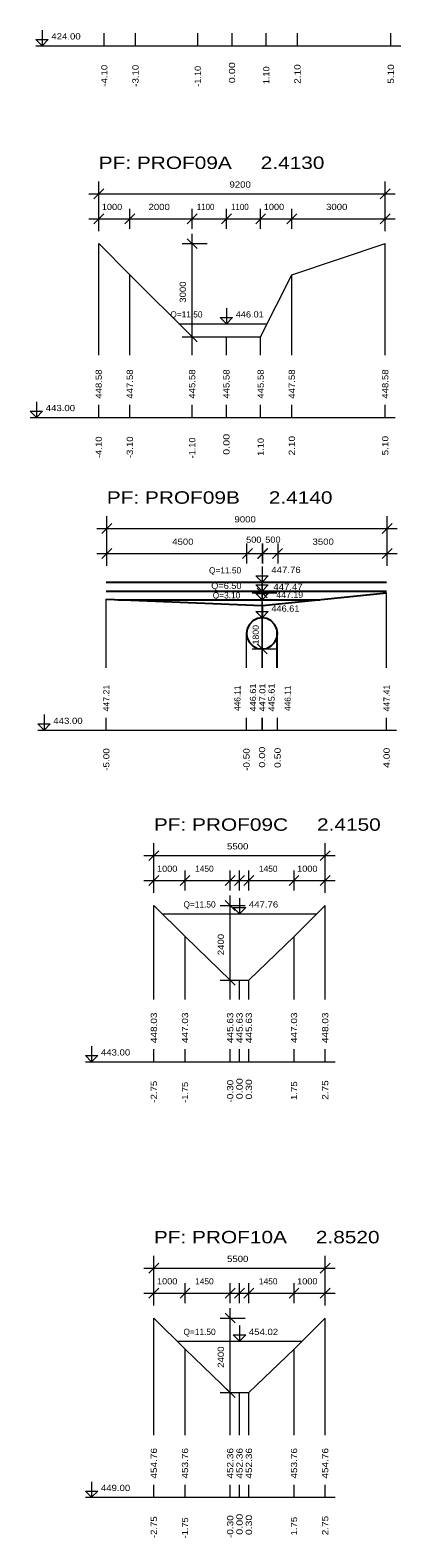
# Model space of a CAD drawing. Extents: x 7 to 442, y -393 to 441.
# Drawn here: x 175.32 to 187.22, y 47.32 to 95.79 of the extents above; entities that cross this region are included whole.
import ezdxf

# ---------------------------------------------------------------- set-up
doc = ezdxf.new("R2010")
doc.units = 0
doc.header["$LTSCALE"] = 0.08
doc.layers.add('7', color=7, linetype='Continuous', lineweight=13)

msp = doc.modelspace()

# ---------------------------------------------------------------- linework, layer by layer
at = {"layer": '7'}
for p, q in [((177.701, 95.289), (177.701, 95.689)), ((178.701, 95.289), (178.701, 95.689)), ((180.701, 95.289), (180.701, 95.689)), ((181.801, 95.289), (181.801, 95.689)), ((182.901, 95.289), (182.901, 95.689)), ((183.901, 95.289), (183.901, 95.689)), ((186.901, 95.289), (186.901, 95.689)), ((175.501, 95.289), (187.221, 95.289)), ((177.361, 90.366), (177.681, 90.686)), ((177.521, 89.326), (177.521, 90.926)), ((186.561, 90.366), (186.881, 90.686)), ((186.721, 89.326), (186.721, 90.926)), ((177.201, 90.526), (187.041, 90.526)), ((177.201, 89.726), (187.041, 89.726)), ((177.361, 89.566), (177.681, 89.886)), ((177.521, 89.406), (177.521, 90.046)), ((178.361, 89.566), (178.681, 89.886)), ((178.521, 89.406), (178.521, 90.046)), ((180.361, 89.566), (180.681, 89.886)), ((180.521, 89.406), (180.521, 90.046)), ((181.461, 89.566), (181.781, 89.886)), ((181.621, 89.406), (181.621, 90.046)), ((182.561, 89.566), (182.881, 89.886)), ((182.721, 89.406), (182.721, 90.046)), ((183.561, 89.566), (183.881, 89.886)), ((183.721, 89.406), (183.721, 90.046)), ((186.561, 89.566), (186.881, 89.886)), ((186.721, 89.406), (186.721, 90.046)), ((180.521, 85.766), (180.521, 89.246)), ((177.521, 85.342), (177.521, 88.926)), ((180.201, 88.926), (181.001, 88.926)), ((180.681, 88.766), (180.361, 89.086)), ((186.721, 85.342), (186.721, 88.926)), ((178.521, 85.342), (178.521, 87.926)), ((183.721, 85.342), (183.721, 87.926)), ((180.095, 86.352), (182.934, 86.352)), ((180.201, 85.926), (181.001, 85.926)), ((180.681, 85.766), (180.361, 86.086)), ((180.521, 85.342), (180.521, 85.926)), ((181.621, 85.342), (181.621, 85.926)), ((182.721, 85.342), (182.721, 85.926)), ((177.521, 83.342), (177.521, 83.742)), ((178.521, 83.342), (178.521, 83.742)), ((180.521, 83.342), (180.521, 83.742)), ((181.621, 83.342), (181.621, 83.742)), ((182.721, 83.342), (182.721, 83.742)), ((183.721, 83.342), (183.721, 83.742)), ((186.721, 83.342), (186.721, 83.742)), ((175.321, 83.342), (187.041, 83.342)), ((177.781, 78.565), (177.781, 80.165)), ((186.781, 78.565), (186.781, 80.165)), ((177.461, 79.765), (187.101, 79.765)), ((177.621, 79.605), (177.941, 79.925)), ((186.621, 79.605), (186.941, 79.925)), ((177.621, 78.805), (177.941, 79.125)), ((177.781, 78.645), (177.781, 79.285)), ((182.141, 78.805), (182.461, 79.125)), ((182.281, 78.645), (182.281, 79.285)), ((182.621, 78.805), (182.941, 79.125)), ((182.621, 78.805), (182.941, 79.125)), ((182.621, 78.805), (182.941, 79.125)), ((182.631, 78.805), (182.951, 79.125)), ((182.631, 78.805), (182.951, 79.125)), ((182.781, 78.645), (182.781, 79.285)), ((182.781, 78.645), (182.781, 79.285)), ((182.781, 78.645), (182.781, 79.285)), ((182.791, 78.645), (182.791, 79.285)), ((182.791, 78.645), (182.791, 79.285)), ((183.101, 78.805), (183.421, 79.125)), ((183.101, 78.805), (183.421, 79.125)), ((183.281, 78.645), (183.281, 79.285)), ((186.621, 78.805), (186.941, 79.125)), ((186.781, 78.645), (186.781, 79.285)), ((177.461, 78.965), (187.101, 78.965)), ((182.445, 77.696), (183.245, 77.696)), ((182.925, 77.536), (182.605, 77.856)), ((182.765, 75.736), (182.765, 78.016)), ((186.765, 75.286), (186.765, 77.696)), ((177.765, 75.286), (177.765, 77.496)), ((182.765, 75.286), (182.765, 77.296)), ((182.775, 75.286), (182.775, 77.296)), ((182.765, 75.286), (182.765, 76.896)), ((182.765, 76.896), (182.775, 76.896)), ((182.775, 75.286), (182.775, 76.896)), ((182.265, 75.286), (182.265, 76.396)), ((183.245, 75.286), (183.245, 76.546)), ((183.265, 75.286), (183.265, 76.396)), ((182.445, 75.896), (183.245, 75.896)), ((182.925, 75.736), (182.605, 76.056)), ((182.765, 75.286), (182.765, 75.896)), ((177.765, 73.286), (177.765, 73.686)), ((182.265, 73.286), (182.265, 73.686)), ((182.765, 73.286), (182.765, 73.686)), ((182.765, 73.286), (182.765, 73.686)), ((182.765, 73.286), (182.765, 73.686)), ((182.775, 73.286), (182.775, 73.686)), ((182.775, 73.286), (182.775, 73.686)), ((183.265, 73.286), (183.265, 73.686)), ((186.765, 73.286), (186.765, 73.686)), ((175.565, 73.286), (187.085, 73.286)), ((179.132, 69.092), (179.452, 69.412)), ((179.292, 68.052), (179.292, 69.652)), ((184.632, 69.092), (184.952, 69.412)), ((184.792, 68.052), (184.792, 69.652)), ((178.972, 69.252), (185.112, 69.252)), ((178.972, 68.452), (185.112, 68.452)), ((179.132, 68.292), (179.452, 68.612)), ((179.292, 68.132), (179.292, 68.772)), ((180.132, 68.292), (180.452, 68.612)), ((180.292, 68.132), (180.292, 68.772)), ((181.582, 68.292), (181.902, 68.612)), ((181.742, 68.132), (181.742, 68.772)), ((181.882, 68.292), (182.202, 68.612)), ((182.042, 68.132), (182.042, 68.772)), ((182.182, 68.292), (182.502, 68.612)), ((182.342, 68.132), (182.342, 68.772)), ((183.632, 68.292), (183.952, 68.612)), ((183.792, 68.132), (183.792, 68.772)), ((184.632, 68.292), (184.952, 68.612)), ((184.792, 68.132), (184.792, 68.772)), ((181.742, 65.092), (181.742, 67.972)), ((179.292, 64.627), (179.292, 67.652)), ((179.56, 67.384), (184.524, 67.384)), ((181.422, 67.652), (182.222, 67.652)), ((181.902, 67.492), (181.582, 67.812)), ((184.792, 64.627), (184.792, 67.652)), ((180.292, 64.627), (180.292, 66.652)), ((183.792, 64.627), (183.792, 66.652)), ((181.422, 65.252), (182.222, 65.252)), ((181.902, 65.092), (181.582, 65.412)), ((181.742, 64.627), (181.742, 65.252)), ((182.042, 64.627), (182.042, 65.252)), ((182.342, 64.627), (182.342, 65.252)), ((179.292, 62.627), (179.292, 63.027)), ((180.292, 62.627), (180.292, 63.027)), ((181.742, 62.627), (181.742, 63.027)), ((182.042, 62.627), (182.042, 63.027)), ((182.342, 62.627), (182.342, 63.027)), ((183.792, 62.627), (183.792, 63.027)), ((184.792, 62.627), (184.792, 63.027)), ((177.092, 62.627), (185.112, 62.627)), ((179.292, 54.789), (179.292, 56.389)), ((184.792, 54.789), (184.792, 56.389)), ((178.972, 55.989), (185.112, 55.989)), ((179.132, 55.829), (179.452, 56.149)), ((184.632, 55.829), (184.952, 56.149)), ((179.132, 55.029), (179.452, 55.349)), ((179.292, 54.869), (179.292, 55.509)), ((180.132, 55.029), (180.452, 55.349)), ((180.292, 54.869), (180.292, 55.509)), ((181.582, 55.029), (181.902, 55.349)), ((181.742, 54.869), (181.742, 55.509)), ((181.882, 55.029), (182.202, 55.349)), ((182.042, 54.869), (182.042, 55.509)), ((182.182, 55.029), (182.502, 55.349)), ((182.342, 54.869), (182.342, 55.509)), ((183.632, 55.029), (183.952, 55.349)), ((183.792, 54.869), (183.792, 55.509)), ((184.632, 55.029), (184.952, 55.349)), ((184.792, 54.869), (184.792, 55.509)), ((178.972, 55.189), (185.112, 55.189)), ((179.292, 50.627), (179.292, 54.389)), ((181.422, 54.389), (182.222, 54.389)), ((181.902, 54.229), (181.582, 54.549)), ((181.742, 51.829), (181.742, 54.709)), ((184.792, 50.627), (184.792, 54.389)), ((180.038, 53.643), (184.046, 53.643)), ((180.292, 50.627), (180.292, 53.389)), ((183.792, 50.627), (183.792, 53.389)), ((181.422, 51.989), (182.222, 51.989)), ((181.902, 51.829), (181.582, 52.149)), ((181.742, 50.627), (181.742, 51.989)), ((182.042, 50.627), (182.042, 51.989)), ((182.342, 50.627), (182.342, 51.989)), ((179.292, 48.627), (179.292, 49.027)), ((180.292, 48.627), (180.292, 49.027)), ((181.742, 48.627), (181.742, 49.027)), ((182.042, 48.627), (182.042, 49.027)), ((182.342, 48.627), (182.342, 49.027)), ((183.792, 48.627), (183.792, 49.027)), ((184.792, 48.627), (184.792, 49.027)), ((177.092, 48.627), (185.112, 48.627))]:
    msp.add_line(p, q, dxfattribs=at)
at = {"layer": '7', "lineweight": 25}
for p, q in [((177.765, 78.043), (186.765, 78.043)), ((177.765, 77.756), (186.765, 77.756)), ((178.151, 77.481), (184.616, 77.481))]:
    msp.add_line(p, q, dxfattribs=at)
at = {"layer": '7'}
for points in [[(175.701, 95.789), (175.701, 95.289), (175.501, 95.489), (175.901, 95.489), (175.701, 95.289)], [(177.521, 88.926), (178.521, 87.926), (180.521, 85.926), (181.621, 85.926), (182.721, 85.926), (183.721, 87.926), (186.721, 88.926)], [(181.621, 86.852), (181.621, 86.352), (181.421, 86.552), (181.821, 86.552), (181.621, 86.352)], [(175.521, 83.842), (175.521, 83.342), (175.321, 83.542), (175.721, 83.542), (175.521, 83.342)], [(182.765, 78.543), (182.765, 78.043), (182.565, 78.243), (182.965, 78.243), (182.765, 78.043)], [(182.765, 78.256), (182.765, 77.756), (182.565, 77.956), (182.965, 77.956), (182.765, 77.756)], [(182.765, 77.981), (182.765, 77.481), (182.565, 77.681), (182.965, 77.681), (182.765, 77.481)], [(182.765, 77.396), (182.765, 76.896), (182.565, 77.096), (182.965, 77.096), (182.765, 76.896)], [(175.765, 73.786), (175.765, 73.286), (175.565, 73.486), (175.965, 73.486), (175.765, 73.286)], [(182.042, 67.884), (182.042, 67.384), (181.842, 67.584), (182.242, 67.584), (182.042, 67.384)], [(179.292, 67.652), (180.292, 66.652), (181.742, 65.252), (182.042, 65.252), (182.342, 65.252), (183.792, 66.652), (184.792, 67.652)], [(177.292, 63.127), (177.292, 62.627), (177.092, 62.827), (177.492, 62.827), (177.292, 62.627)], [(179.292, 54.389), (180.292, 53.389), (181.742, 51.989), (182.042, 51.989), (182.342, 51.989), (183.792, 53.389), (184.792, 54.389)], [(182.042, 54.143), (182.042, 53.643), (181.842, 53.843), (182.242, 53.843), (182.042, 53.643)], [(177.292, 49.127), (177.292, 48.627), (177.092, 48.827), (177.492, 48.827), (177.292, 48.627)]]:
    msp.add_lwpolyline(points, dxfattribs=at)
at = {"layer": '7', "lineweight": 25}
msp.add_lwpolyline([(177.765, 77.496), (182.765, 77.296), (182.765, 76.896), (182.615, 76.876), (182.475, 76.796), (182.365, 76.686), (182.285, 76.546), (182.265, 76.396), (182.285, 76.246), (182.365, 76.106), (182.475, 75.996), (182.615, 75.916), (182.765, 75.896), (182.915, 75.916), (183.055, 75.996), (183.165, 76.106), (183.245, 76.246), (183.265, 76.396), (183.245, 76.546), (183.165, 76.686), (183.055, 76.796), (182.915, 76.876), (182.775, 76.896), (182.775, 77.296), (186.765, 77.696)], dxfattribs=at)

# ---------------------------------------------------------------- texts
at = {"layer": '7'}
for s, height, width, p in [('424.00', 0.2, 1.15, (176.001, 95.489)), ('PF: PROF09A     2.4130', 0.4, 1.25, (177.521, 91.326)), ('9200', 0.2, 1.15, (181.721, 90.726)), ('1000', 0.2, 1.1, (177.621, 90.006)), ('2000', 0.2, 1.15, (179.121, 90.006)), ('1100', 0.2, 0.95, (180.671, 90.006)), ('1100', 0.2, 0.95, (181.771, 90.006)), ('1000', 0.2, 1.1, (182.821, 90.006)), ('3000', 0.2, 1.15, (184.821, 90.006)), ('446.01', 0.2, 1.1, (181.921, 86.552)), ('443.00', 0.2, 1.15, (175.821, 83.542)), ('PF: PROF09B     2.4140', 0.4, 1.25, (177.781, 80.565)), ('9000', 0.2, 1.15, (181.881, 79.965)), ('500', 0.2, 1.1, (182.255, 79.31)), ('500', 0.2, 1.1, (182.869, 79.31)), ('4500', 0.2, 1.15, (179.881, 79.245)), ('3500', 0.2, 1.15, (184.386, 79.245)), ('447.76', 0.2, 1.15, (183.065, 78.34)), ('Q=6.50', 0.2, 1.1, (181.133, 77.827)), ('447.47', 0.2, 1.15, (183.13, 77.794)), ('447.19', 0.2, 1.05, (183.226, 77.536)), ('446.61', 0.2, 1.1, (183.065, 77.096)), ('443.00', 0.2, 1.15, (176.065, 73.486)), ('PF: PROF09C     2.4150', 0.4, 1.25, (179.292, 70.052)), ('5500', 0.2, 1.15, (181.642, 69.452)), ('1000', 0.2, 1.1, (179.392, 68.732)), ('1000', 0.2, 1.1, (183.892, 68.732)), ('447.76', 0.2, 1.15, (182.342, 67.584)), ('443.00', 0.2, 1.15, (177.592, 62.827)), ('PF: PROF10A     2.8520', 0.4, 1.25, (179.292, 56.789)), ('5500', 0.2, 1.15, (181.642, 56.189)), ('1000', 0.2, 1.1, (179.392, 55.469)), ('1000', 0.2, 1.1, (183.892, 55.469)), ('454.02', 0.2, 1.15, (182.342, 53.843)), ('449.00', 0.2, 1.15, (177.592, 48.827))]:
    msp.add_text(s, height=height, dxfattribs=dict(at, width=width)).set_placement(p)
for s, width, p in [(' -4.10 ', 1.15, (177.801, 93.889)), (' -3.10 ', 1.15, (178.801, 93.889)), (' -1.10 ', 1.1, (180.801, 93.889)), ('  0.00 ', 1.3, (181.901, 93.889)), ('  1.10 ', 1.1, (183.001, 93.889)), ('  2.10 ', 1.2, (184.001, 93.889)), ('  5.10 ', 1.2, (187.001, 93.889)), ('3000', 1.15, (180.321, 87.026)), ('448.58 ', 1.15, (177.621, 83.942)), ('447.58 ', 1.15, (178.621, 83.942)), ('445.58 ', 1.15, (180.621, 83.942)), ('445.58 ', 1.15, (181.721, 83.942)), ('445.58 ', 1.15, (182.821, 83.942)), ('447.58 ', 1.15, (183.821, 83.942)), ('448.58 ', 1.15, (186.821, 83.942)), (' -4.10 ', 1.15, (177.621, 81.942)), (' -3.10 ', 1.15, (178.621, 81.942)), (' -1.10 ', 1.1, (180.621, 81.942)), ('  0.00 ', 1.3, (181.721, 81.942)), ('  1.10 ', 1.1, (182.821, 81.942)), ('  2.10 ', 1.2, (183.821, 81.942)), ('  5.10 ', 1.2, (186.821, 81.942)), ('1800', 1.05, (182.662, 76.041)), ('447.21 ', 1.05, (177.865, 73.886)), ('446.61 ', 1.1, (182.574, 73.886)), ('447.01 ', 1.1, (182.875, 73.886)), ('445.61 ', 1.1, (183.172, 73.886)), ('447.41 ', 1.05, (186.865, 73.886)), ('  0.00 ', 1.3, (182.865, 71.886)), ('  0.00 ', 1.3, (182.865, 71.886)), ('  0.50 ', 1.25, (183.365, 71.886)), ('  4.00 ', 1.25, (186.865, 71.886)), (' -5.00 ', 1.2, (177.865, 71.886)), (' -0.50 ', 1.2, (182.365, 71.886)), ('2400', 1.15, (181.542, 66.052)), ('448.03 ', 1.2, (179.392, 63.227)), ('447.03 ', 1.2, (180.392, 63.227)), ('445.63 ', 1.2, (181.842, 63.227)), ('445.63 ', 1.2, (182.142, 63.227)), ('445.63 ', 1.2, (182.442, 63.227)), ('447.03 ', 1.2, (183.892, 63.227)), ('448.03 ', 1.2, (184.892, 63.227)), ('  0.00 ', 1.3, (182.142, 61.227)), ('  0.30 ', 1.25, (182.442, 61.227)), (' -2.75 ', 1.15, (179.392, 61.227)), (' -1.75 ', 1.1, (180.392, 61.227)), (' -0.30 ', 1.2, (181.842, 61.227)), ('  1.75 ', 1.15, (183.892, 61.227)), ('  2.75 ', 1.2, (184.892, 61.227)), ('2400', 1.15, (181.542, 52.789)), ('454.76 ', 1.2, (179.392, 49.227)), ('453.76 ', 1.2, (180.392, 49.227)), ('452.36 ', 1.2, (181.842, 49.227)), ('452.36 ', 1.2, (182.142, 49.227)), ('452.36 ', 1.2, (182.442, 49.227)), ('453.76 ', 1.2, (183.892, 49.227)), ('454.76 ', 1.2, (184.892, 49.227)), (' -2.75 ', 1.15, (179.392, 47.227)), (' -0.30 ', 1.2, (181.842, 47.227)), ('  0.00 ', 1.3, (182.142, 47.227)), ('  0.30 ', 1.25, (182.442, 47.227)), ('  1.75 ', 1.15, (183.892, 47.227)), ('  2.75 ', 1.2, (184.892, 47.227)), (' -1.75 ', 1.1, (180.392, 47.227))]:
    msp.add_text(s, height=0.2, rotation=90, dxfattribs=dict(at, width=width)).set_placement(p)
for s, p in [('Q=11.50', (179.821, 86.552)), ('Q=11.50', (181.062, 78.324)), ('Q=3.10', (181.182, 77.52)), ('1450', (180.617, 68.732)), ('1450', (182.667, 68.732)), ('Q=11.50', (180.242, 67.584)), ('1450', (180.617, 55.469)), ('1450', (182.667, 55.469)), ('Q=11.50', (180.242, 53.843))]:
    msp.add_text(s, height=0.2, dxfattribs=at).set_placement(p)
for p in [(182.074, 73.902), (183.688, 73.902)]:
    msp.add_text('446.11 ', height=0.2, rotation=90, dxfattribs=at).set_placement(p)

doc.saveas('drawing.dxf')
